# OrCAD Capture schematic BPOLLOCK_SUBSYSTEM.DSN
size A; title: Stepper Motor Subsystem-Bradley Pollock; rev: 1; company: Bradley Pollock; note: 1
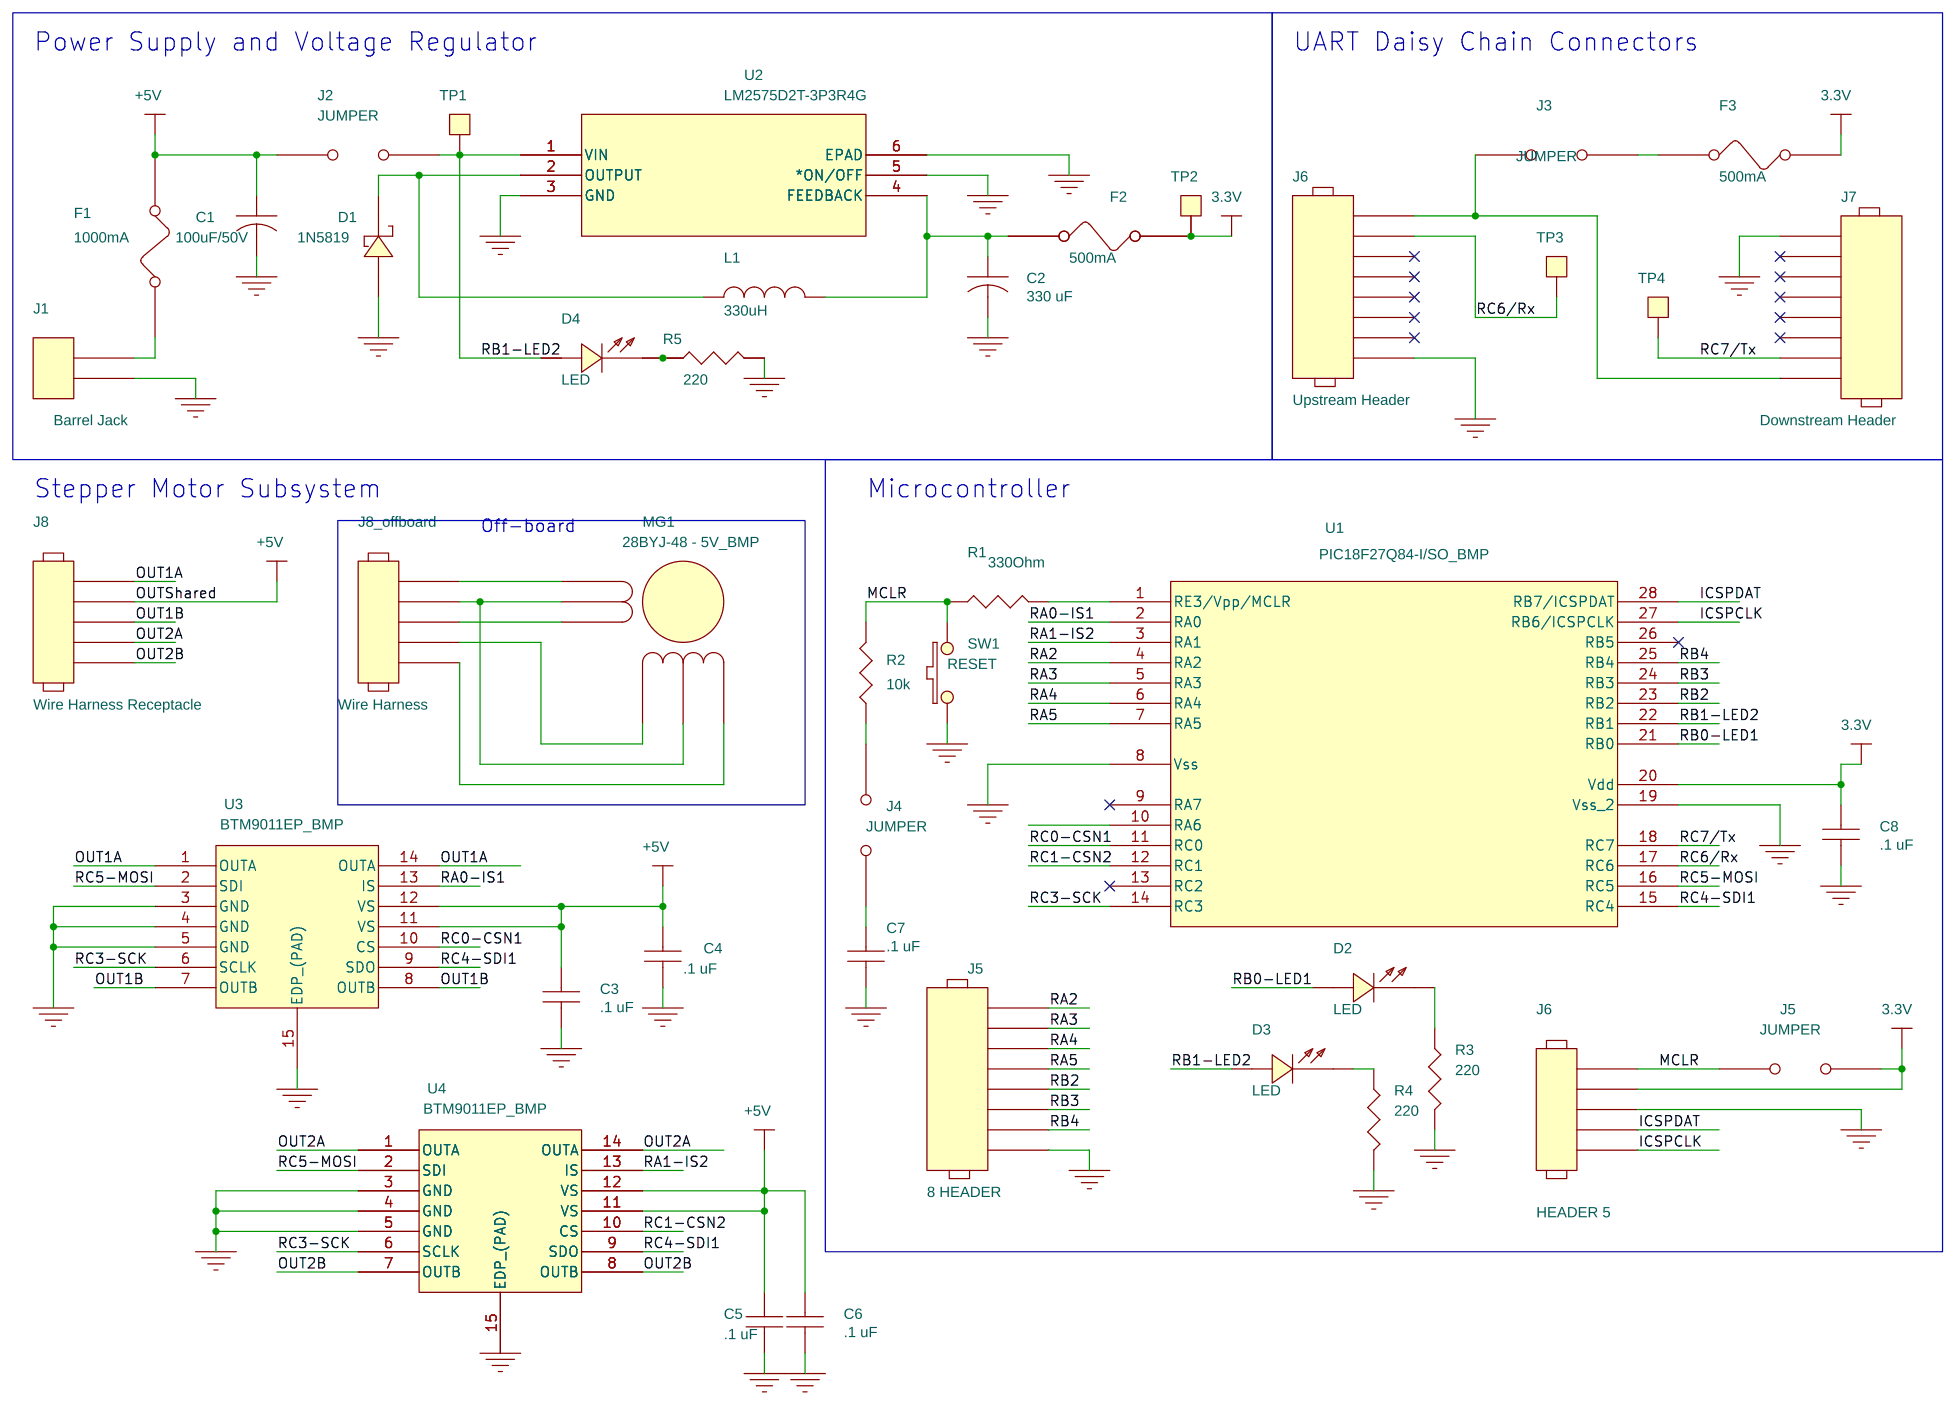
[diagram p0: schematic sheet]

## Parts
C1  100uF/50V
C2  330 uF
C3  .1 uF
C4  .1 uF
C5  .1 uF
C6  .1 uF
C7  .1 uF
C8  .1 uF
D1  1N5819
D2  LED
D3  LED
D4  LED
F1  1000mA
F2  500mA
F3  500mA
J1  Barrel Jack
J2  JUMPER
J3  JUMPER
J4  JUMPER
J5  JUMPER
J6  HEADER 5
J7  Downstream Header
J8  Wire Harness Receptacle
J8_offboard  Wire Harness
L1  330uH
MG1  28BYJ-48 - 5V_BMP
R1  330Ohm
R2  10k
R3  220
R4  220
R5  220
SW1  RESET
TP1  T POINT S
TP2  T POINT S
TP3  T POINT S
TP4  T POINT S
U1  PIC18F27Q84-I/SO_BMP
U2  LM2575D2T-3P3R4G  [D2PAK-5_ONS]
U3  BTM9011EP_BMP
U4  BTM9011EP_BMP

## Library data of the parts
C1 C2 = CAP
C3-C8 = CAP_NP
D1 = DIODE_SCHOTTKY
D2-D4 = LED
F1-F3 = FUSE
J1 = CON2_0
J2-J5 = JUMPER
J6 J8 J8_offboard = HEADER_5
J7 = 8_HEADER
L1 = INDUCTOR
MG1 = MOTOR_STEPPER
R1-R5 = R
SW1 = SW_PUSHBUTTON
TP1-TP4 = T_POINT_S
U1 = PIC18F27Q84-ISO_BMP
U2 = LM2575D2T-3P3R4G
U3 U4 = BTM9011EP_BMP

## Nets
3.3V: C8.1 F2.1 F3.1 J5.2 J6.2 TP2.1(TP) TP3.1(TP) U1.5(RA3) U1.17(RC6) U1.20(Vdd)
+5V: C1.1 C3.1 C4.1 C5.1 C6.1 F1.1 J2.2 J8.2 U3.11(VS) U3.12(VS) U4.11(VS) U4.12(VS)
GND: C1.2 C2.2 C3.2 C4.2 C5.2 C6.2 C7.2 C8.2 D1.1(ANODE) J1.1 J5.8 J6.3 J6.8 J7.8 R3.2 R4.2 R5.2 SW1.1 U1.8(Vss) U1.19(Vss_2) U2.3(GND) U2.5(*ON/OFF) U2.6(EPAD) U3.3(GND) U3.4(GND) U3.5(GND) U3.15(EDP_(PAD)) U4.3(GND) U4.4(GND) U4.5(GND) U4.15(EDP_(PAD))
ICSPCLK: J6.5 U1.27(RB6/ICSPCLK)
ICSPDAT: J6.4 U1.28(RB7/ICSPDAT)
MCLR: J3.1 J5.1 J6.1 J7.1 R1.1 R2.2 SW1.2 U1.4(RA2)
OUT1A: J8.1 U3.1(OUTA) U3.14(OUTA)
OUT1B: J8.3 U3.7(OUTB) U3.8(OUTB)
OUT2A: J8.4 U4.1(OUTA) U4.14(OUTA)
OUT2B: J8.5 U4.7(OUTB) U4.8(OUTB)
RA0-IS1: U1.2(RA0) U3.13(IS)
RA1-IS2: U1.3(RA1) U4.13(IS)
RA4: J5.3 U1.6(RA4)
RA5: J5.4 U1.7(RA5)
RB0-LED1: D2.2(ANODE) U1.21(RB0)
RB1-LED2: D3.2(ANODE) D4.2(ANODE) J2.1 TP1.1(TP) U1.22(RB1) U2.1(VIN)
RB2: J5.5 U1.23(RB2)
RB3: J5.6 U1.24(RB3)
RB4: J5.7 U1.25(RB4)
RC0-CSN1: U1.11(RC0) U3.10(CS)
RC1-CSN2: U1.12(RC1) U4.10(CS)
RC3-SCK: U1.14(RC3) U3.6(SCLK) U4.6(SCLK)
RC4-SDI1: U1.15(RC4) U3.9(SDO) U4.9(SDO)
RC5-MOSI: U1.16(RC5) U3.2(SDI) U4.2(SDI)
RC7/Tx: J7.2 TP4.1(TP) U1.18(RC7)
N02724: D1.2(CATHODE) L1.1 U2.2(OUTPUT)
N02756: C2.1 F2.2 L1.2 U2.4(FEEDBACK)
N06953: R1.2 U1.1(RE3/Vpp/MCLR)
N07371: C7.1 J4.1
N07637: J4.2 R2.1
N08603: F3.2 J3.2
N09521: J8_offboard.2 MG1.2 MG1.5
N13847: J8_offboard.1 MG1.1
N13851: J8_offboard.3 MG1.3
N13855: J8_offboard.4 MG1.4
N13864: J8_offboard.5 MG1.6
N15027: D2.1(CATHODE) R3.1
N15031: D3.1(CATHODE) R4.1
N18381: F1.2 J1.2
N23462: D4.1(CATHODE) R5.1

Not connected (* = marked no-connect by the designer): J6 6* 7*; J7 3* 4* 5* 6* 7*; U1 9(RA7)* 10(RA6) 13(RC2)* 26(RB5)*

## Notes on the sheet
- Power Supply and Voltage Regulator
- UART Daisy Chain Connectors
- Stepper Motor Subsystem
- Microcontroller
- Off-board
